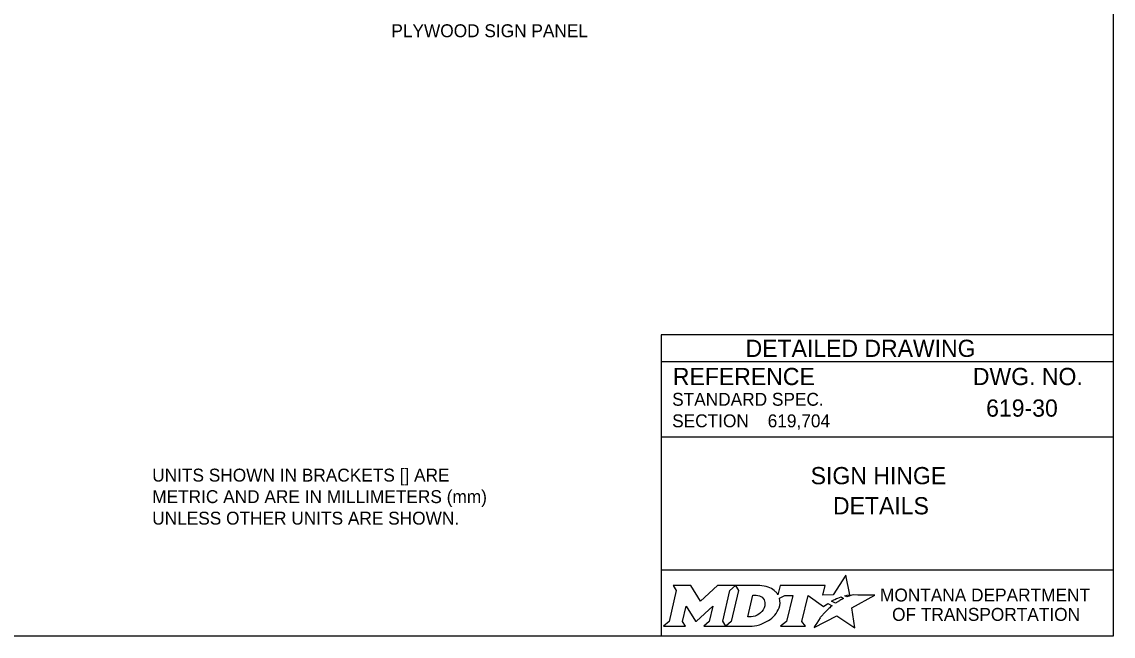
# Model space of a CAD drawing. Extents: x 49991.4 to 50021, y 49987.6 to 50011.4.
# Drawn here: x 50011.68 to 50016.75, y 49987.8 to 49990.65 of the extents above; entities that cross this region are included whole.
import ezdxf

# ---------------------------------------------------------------- set-up
doc = ezdxf.new("R2010")
doc.units = 0
for name, color, linetype in [('Default', 7, 'Continuous'), ('Level 1', 7, 'Continuous'), ('Level 2', 7, 'Continuous'), ('Level 5', 7, 'Continuous')]:
    doc.layers.add(name, color=color, linetype=linetype)

msp = doc.modelspace()

# ---------------------------------------------------------------- linework, layer by layer
at = {"layer": 'Default'}
for points in [[(50015.5126, 49987.9811), (50015.5023, 49987.9867), (50015.5139, 49987.9895), (50015.5255, 49987.9915), (50015.5081, 49988.0816), (50015.4486, 49987.9903), (50015.4013, 49987.9896), (50015.4116, 49988.0337), (50015.2024, 49988.0338), (50015.1923, 49987.9913), (50015.1865, 49987.9996)], [(50014.7056, 49988.0338), (50014.7197, 49988.0104), (50014.6862, 49987.8671), (50014.6605, 49987.8446), (50014.7621, 49987.8446), (50014.7486, 49987.8674), (50014.7648, 49987.9375), (50014.8085, 49987.8685), (50014.8138, 49987.8685), (50014.8889, 49987.938), (50014.8725, 49987.8669), (50014.8478, 49987.8449), (50014.9494, 49987.8449), (50014.9356, 49987.8682), (50014.9688, 49988.0106)], [(50014.9688, 49988.0106), (50014.9941, 49988.0338), (50014.9117, 49988.0338), (50014.8321, 49987.9608), (50014.7876, 49988.0335), (50014.7056, 49988.0338)], [(50015.1077, 49988.0338), (50014.9941, 49988.0338), (50015.0088, 49988.0109), (50014.9749, 49987.8671), (50014.9494, 49987.8449), (50015.06, 49987.8449)], [(50015.1317, 49987.9471), (50015.1305, 49987.939), (50015.1273, 49987.9297), (50015.1231, 49987.9215), (50015.1175, 49987.914), (50015.111, 49987.9071), (50015.1031, 49987.9008), (50015.0948, 49987.8961), (50015.0857, 49987.8922), (50015.0766, 49987.8899), (50015.0674, 49987.889), (50015.0515, 49987.889), (50015.0751, 49987.989), (50015.0911, 49987.989), (50015.0987, 49987.9884), (50015.1063, 49987.9865), (50015.1129, 49987.9835), (50015.119, 49987.9793), (50015.1238, 49987.9743), (50015.1275, 49987.9683), (50015.1302, 49987.9621), (50015.1318, 49987.9547), (50015.1318, 49987.9517), (50015.1317, 49987.9471)], [(50015.1991, 49987.9747), (50015.2237, 49987.9878), (50015.2606, 49987.9878), (50015.232, 49987.8673), (50015.2045, 49987.8446), (50015.3207, 49987.8446), (50015.3037, 49987.8675), (50015.3319, 49987.9877), (50015.4032, 49987.936), (50015.4243, 49987.9511), (50015.444, 49987.9402)], [(50015.3882, 49987.8843), (50015.3729, 49987.8599), (50015.3682, 49987.8524), (50015.3624, 49987.8438), (50015.3601, 49987.8395), (50015.4654, 49987.8926), (50015.5493, 49987.8375), (50015.5362, 49987.9302), (50015.6431, 49987.9886), (50015.5938, 49987.9894), (50015.5637, 49987.9898), (50015.5429, 49987.9901), (50015.5361, 49987.9886), (50015.5312, 49987.9874), (50015.5228, 49987.9851), (50015.5126, 49987.9811)], [(50015.4622, 49987.9535), (50015.4598, 49987.9518), (50015.4415, 49987.9614), (50015.4518, 49987.9671), (50015.4559, 49987.9693), (50015.4645, 49987.9733), (50015.4702, 49987.9759), (50015.4781, 49987.9789), (50015.4854, 49987.9816), (50015.4972, 49987.9742), (50015.4932, 49987.9721), (50015.4886, 49987.9696), (50015.4844, 49987.9674), (50015.4794, 49987.9645), (50015.4775, 49987.9634), (50015.4748, 49987.9618), (50015.4723, 49987.9604), (50015.47, 49987.9588), (50015.4674, 49987.957), (50015.4647, 49987.9552), (50015.4622, 49987.9535)], [(50015.1057, 49987.8522), (50015.1141, 49987.8548), (50015.1271, 49987.8602), (50015.1475, 49987.8712)], [(50015.4021, 49987.9004), (50015.4021, 49987.9004)]]:
    msp.add_lwpolyline(points, dxfattribs=at)
for centre, radius, start, end in [((50015.1308, 49987.9554), 0.0709, 339.5329, 15.8582), ((50015.0868, 49987.9727), 0.1183, 300.9103, 339.1383)]:
    msp.add_arc(centre, radius, start, end, dxfattribs=at)
for centre, major_axis, ratio, start_param, end_param in [((50015.1056, 49987.9864), (0.0834, -0.0037), 0.568097, 0.61298, 1.570796), ((50015.1612, 49987.9937), (0.0361, -0.0295), 0.469099, 1.225588, 1.570796), ((50015.4119, 49987.9106), (-0.0098, -0.0102), 0.016458, 3.141593, 6.279097), ((50015.4329, 49987.9305), (-0.0112, -0.0097), 0.021651, 3.157348, 6.283185), ((50015.0603, 49987.9932), (0, 0.1484), 0.987302, 3.139398, 3.456847), ((50015.3952, 49987.8923), (-0.00694, -0.00806), 0.008222, 0, 3.137361)]:
    msp.add_ellipse(centre, major_axis=major_axis, ratio=ratio, start_param=start_param, end_param=end_param, dxfattribs=at)
at = {"layer": 'Level 1'}
msp.add_lwpolyline([(49999.3835, 49998.9992), (50016.7501, 49998.9992), (50016.7501, 49987.7988), (49999.3835, 49987.7988)], close=True, dxfattribs=at)
at = {"layer": 'Level 5'}
for p, q in [((50016.7501, 49989.1988), (50014.6501, 49989.1988)), ((50014.6501, 49989.1988), (50014.6501, 49987.7988)), ((50016.7501, 49989.0738), (50014.6501, 49989.0738)), ((50016.3862, 49988.8587), (50016.3862, 49988.8587)), ((50015.1444, 49988.7993), (50015.1444, 49988.7993)), ((50016.7501, 49988.7238), (50014.6501, 49988.7238)), ((50015.7001, 49988.4747), (50015.7001, 49988.4747)), ((50016.7501, 49988.1057), (50014.6501, 49988.1057))]:
    msp.add_line(p, q, dxfattribs=at)

# ---------------------------------------------------------------- texts
at = {"layer": 'Default'}
for s, p in [('MONTANA DEPARTMENT', (50015.6663, 49987.96)), ('OF TRANSPORTATION', (50015.7225, 49987.87))]:
    msp.add_text(s, height=0.06, dxfattribs=at).set_placement(p)
at = {"layer": 'Level 2'}
for s, height, p in [('PLYWOOD SIGN PANEL', 0.06, (50013.3953, 49990.5819)), ('619-30', 0.08, (50016.1596, 49988.8187)), ('619,704', 0.06, (50015.1444, 49988.7693)), ('UNITS SHOWN IN BRACKETS [] ARE ', 0.06, (50012.2839, 49988.5171)), ('SIGN HINGE', 0.08, (50015.3441, 49988.5047)), ('METRIC AND ARE IN MILLIMETERS (mm) ', 0.06, (50012.2839, 49988.4171)), ('DETAILS', 0.08, (50015.4479, 49988.3647)), ('UNLESS OTHER UNITS ARE SHOWN.', 0.06, (50012.2839, 49988.3171))]:
    msp.add_text(s, height=height, dxfattribs=at).set_placement(p)
at = {"layer": 'Level 5'}
for s, height, p in [('DETAILED DRAWING', 0.0799, (50015.0418, 49989.0963)), ('REFERENCE', 0.08, (50014.7037, 49988.9654)), ('DWG. NO.', 0.08, (50016.0979, 49988.9654)), ('STANDARD SPEC.', 0.06, (50014.7004, 49988.8694)), ('SECTION', 0.06, (50014.7004, 49988.7694))]:
    msp.add_text(s, height=height, dxfattribs=at).set_placement(p)

doc.saveas('drawing.dxf')
